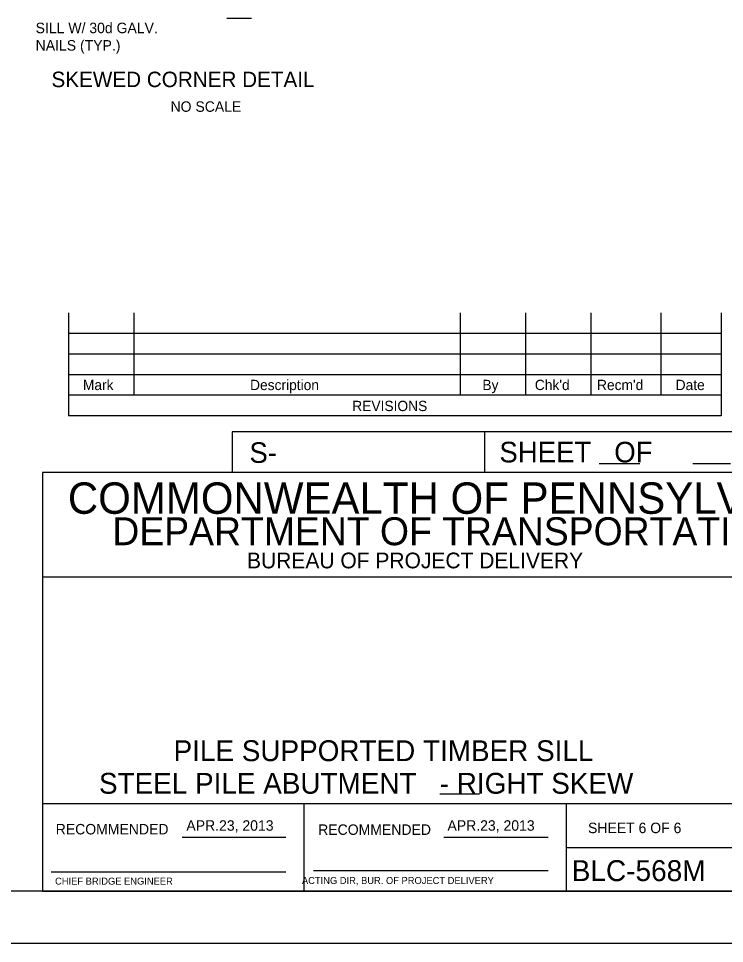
# Model space of a CAD drawing. Extents: x 638304 to 640306, y 296653 to 298435.
# Drawn here: x 639895.6 to 640097.9, y 296653.5 to 296918.5 of the extents above; entities that cross this region are included whole.
import ezdxf

# ---------------------------------------------------------------- set-up
doc = ezdxf.new("R2010")
doc.units = 0
for name, color, linetype in [('2', 7, 'Continuous'), ('4', 7, 'Continuous'), ('Level 4', 7, 'Continuous'), ('Level 5', 7, 'Continuous'), ('PLT-BNDY', 7, 'Continuous')]:
    doc.layers.add(name, color=color, linetype=linetype)

msp = doc.modelspace()

# ---------------------------------------------------------------- linework, layer by layer
at = {"layer": '2'}
for p, q in [((639909.92, 296834.15), (639909.92, 296804.62)), ((639928.62, 296834.15), (639928.62, 296810.53)), ((640022.13, 296834.15), (640022.13, 296810.53)), ((640040.83, 296834.15), (640040.83, 296810.53)), ((640059.53, 296834.15), (640059.53, 296810.53)), ((640079.59, 296834.15), (640079.59, 296810.53)), ((640096.94, 296834.15), (640096.94, 296804.62)), ((640096.94, 296828.24), (639909.92, 296828.24)), ((640096.94, 296822.34), (639909.92, 296822.34)), ((640096.94, 296816.43), (639909.92, 296816.43)), ((640096.94, 296810.53), (639909.92, 296810.53)), ((640096.94, 296804.62), (639909.92, 296804.62)), ((640102.46, 296800.11), (639956.78, 296800.11)), ((639956.78, 296800.11), (639956.78, 296788.46)), ((640029.09, 296800.11), (640029.09, 296788.46)), ((640061.95, 296791), (640073.6, 296791)), ((640088.83, 296791), (640099.56, 296791)), ((640102.46, 296788.46), (639902.46, 296788.46)), ((639902.46, 296788.46), (639902.46, 296668.46)), ((640102.46, 296758.46), (639902.46, 296758.46)), ((640102.46, 296693.46), (639902.46, 296693.46)), ((639977.46, 296668.46), (639977.46, 296693.46)), ((640052.46, 296693.46), (640052.46, 296668.46)), ((639942.42, 296683.96), (639972.19, 296683.96)), ((640017.42, 296683.96), (640047.33, 296683.96)), ((640052.46, 296680.96), (640102.46, 296680.96)), ((639904.96, 296673.96), (639972.19, 296673.96)), ((639980.08, 296674.33), (640047.33, 296674.33)), ((640102.46, 296668.46), (639316.46, 296668.46)), ((639902.46, 296668.46), (640102.46, 296668.46))]:
    msp.add_line(p, q, dxfattribs=at)
at = {"layer": '4'}
msp.add_line((640016.27, 296696.38), (640027.63, 296696.38), dxfattribs=at)
at = {"layer": 'Level 4'}
msp.add_line((639962.34, 296918.51), (639955.29, 296918.51), dxfattribs=at)
at = {"layer": 'PLT-BNDY'}
msp.add_lwpolyline([(639276.46, 297247.46), (640117.46, 297247.46), (640117.46, 296653.46), (639276.46, 296653.46)], close=True, dxfattribs=at)

# ---------------------------------------------------------------- texts
at = {"layer": '2'}
for s, height, p in [('Mark', 2.952, (639914.02, 296812.03)), ('Description', 2.9523, (639961.92, 296812.03)), ('By', 2.952, (640028.49, 296812.03)), ("Chk'd", 2.952, (640043.52, 296812.03)), ("Recm'd", 2.953, (640061.33, 296812.03)), ('Date', 2.952, (640083.86, 296812.03)), ('REVISIONS', 2.952, (639991.2, 296806.01)), ('S-', 5.905, (639961.73, 296791.17)), ('COMMONWEALTH OF PENNSYLVANIA', 9, (639909.71, 296776.58)), ('DEPARTMENT OF TRANSPORTATION', 8.0002, (639922.46, 296767.58)), ('BUREAU OF PROJECT DELIVERY', 4.5, (639961.05, 296760.96)), ('STEEL PILE ABUTMENT   - RIGHT SKEW', 5.9728, (639918.63, 296696.37)), ('APR.23, 2013', 3, (639943.67, 296685.77)), ('APR.23, 2013', 3, (640018.48, 296685.77)), ('SHEET 6 OF 6', 3, (640058.75, 296685.08)), ('BLC-568M', 6, (640054.08, 296671.33)), ('CHIEF BRIDGE ENGINEER', 2.0002, (639906.05, 296670.33)), ('  ACTING DIR, BUR. OF PROJECT DELIVERY', 2.0002, (639975.3, 296670.51))]:
    msp.add_text(s, height=height, dxfattribs=at).set_placement(p)
for s, height, p in [('SHEET   OF', 5.907, (640033.35, 296791.31)), ('RECOMMENDED', 3, (639906.23, 296684.71)), ('RECOMMENDED', 3, (639981.44, 296684.58))]:
    msp.add_text(s, height=height, rotation=360, dxfattribs=at).set_placement(p)
at = {"layer": '4'}
for s, height, p in [('SKEWED CORNER DETAIL', 4.4294, (639905.02, 296898.84)), ('NO SCALE', 3, (639939.13, 296891.77)), ('PILE SUPPORTED TIMBER SILL', 5.9728, (639940.01, 296705.71))]:
    msp.add_text(s, height=height, dxfattribs=at).set_placement(p)
at = {"layer": 'Level 5'}
for s, p in [('SILL W/ 30d GALV.', (639900.48, 296914.3)), ('NAILS (TYP.)', (639900.48, 296909.31))]:
    msp.add_text(s, height=3.0001, dxfattribs=at).set_placement(p)

doc.saveas('drawing.dxf')
